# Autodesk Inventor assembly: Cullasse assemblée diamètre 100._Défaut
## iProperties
Shininess: 64.0
Length Units: 11269
Angle Units: 11279
Time Units: 11290
Mass Units: 11283
Length Display Precision: 3
Angle Display Precision: 2
Compacted: True
Created: 2006-01
Part Number: Cullasse assemblée diamètre 100._Défaut
Document SubType Name: Assembly
Designer: riri
Density: 0.0
Volumn: 0.0
Area: 0.0
PropertySet Name: Model Information
Control State: 0
Master: False
Checked Out: False
Author: riri
